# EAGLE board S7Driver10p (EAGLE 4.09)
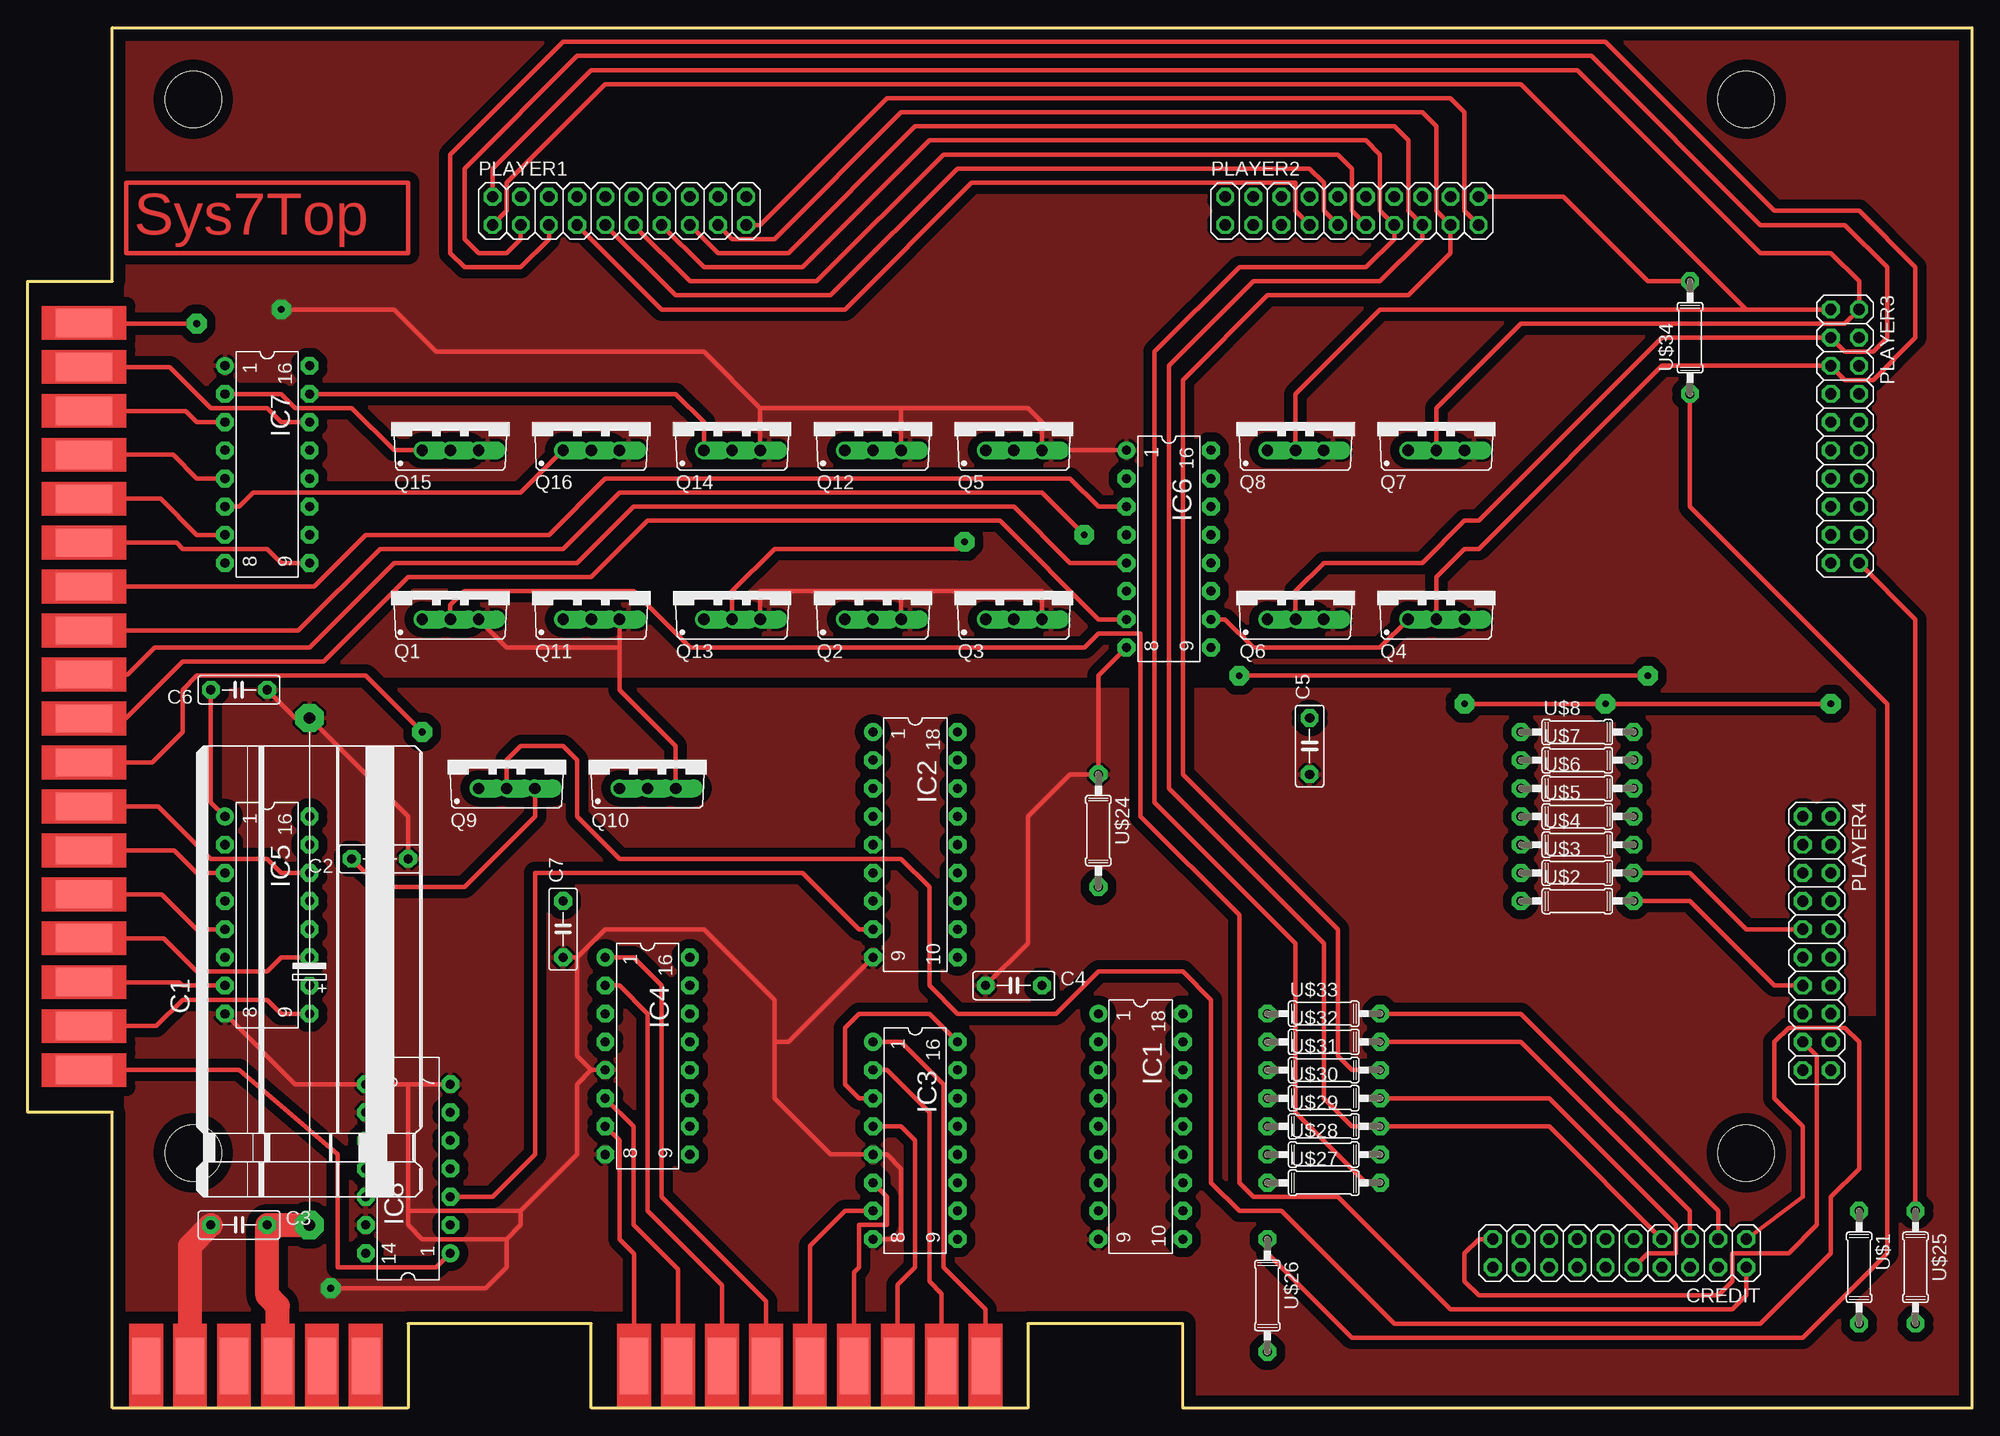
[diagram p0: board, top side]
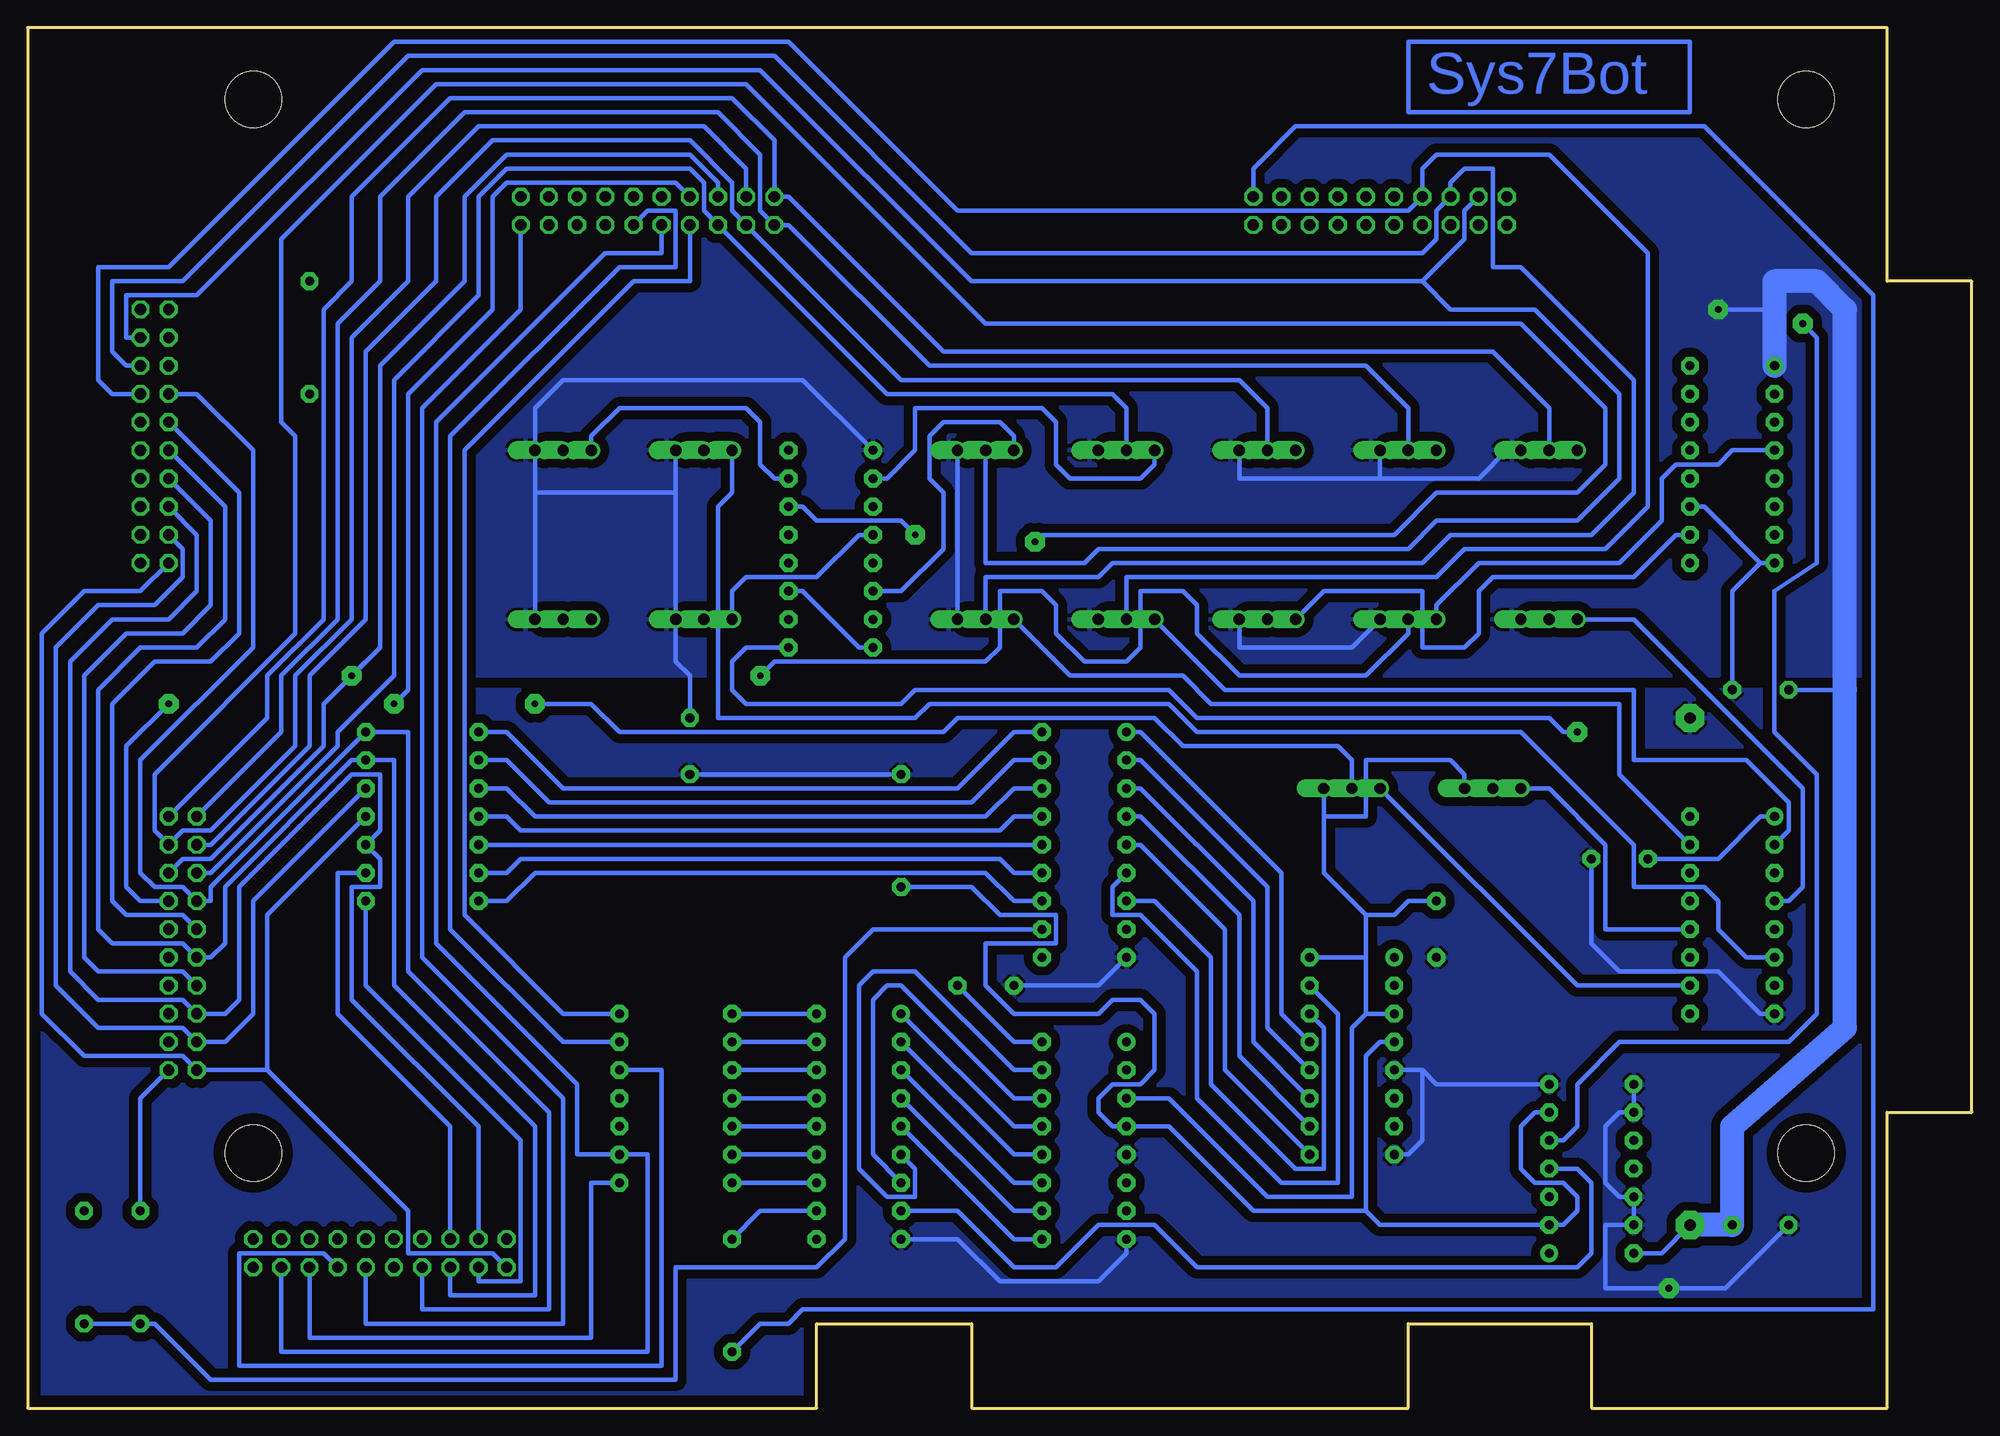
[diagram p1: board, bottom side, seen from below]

Size 175.26 x 124.46 mm. Coordinates in mm from the lower left corner, seen from the top.
Outline: 7.62,0 7.62,26.67 0,26.67 0,101.6 7.62,101.6 7.62,124.46 175.26,124.46 175.26,0 104.14,0 104.14,7.62 90.17,7.62 90.17,0 50.8,0 50.8,7.62 34.29,7.62 34.29,0 7.62,0
Copper layers used: Top, Bottom
Holes 5.08 mm at 14.92,23 154.92,23 154.92,118 14.92,118

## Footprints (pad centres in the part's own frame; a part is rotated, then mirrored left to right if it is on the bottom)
PLATINE9 = smd 2.54 x 5.08: 1 0,0; 2 3.962,0; 3 7.925,0; 4 11.887,0; 5 15.85,0; 6 19.812,0; 7 23.774,0; 8 27.737,0; 9 31.699,0
E-45 = drill 1.016 pad 2.54 octagon: 1 0,0; 2 45.72,0
C5B2,5 = drill 0.813 pad 1.6 octagon: 1 -2.54,0; 2 2.54,0
2X10 = drill 1.016 pad 1.6 octagon: 1 -11.43,-1.27; 2 -11.43,1.27; 3 -8.89,-1.27; 4 -8.89,1.27; 5 -6.35,-1.27; 6 -6.35,1.27; 7 -3.81,-1.27; 8 -3.81,1.27; 9 -1.27,-1.27; 10 -1.27,1.27; 11 1.27,-1.27; 12 1.27,1.27; 13 3.81,-1.27; 14 3.81,1.27; 15 6.35,-1.27; 16 6.35,1.27; 17 8.89,-1.27; 18 8.89,1.27; 19 11.43,-1.27; 20 11.43,1.27
DIL18 = drill 0.813 pad 1.6 round: 1 -10.16,-3.81 | drill 0.813 pad 1.6 octagon: 2 -7.62,-3.81; 3 -5.08,-3.81; 4 -2.54,-3.81; 5 0,-3.81; 6 2.54,-3.81; 7 5.08,-3.81; 8 7.62,-3.81; 9 10.16,-3.81; 10 10.16,3.81; 11 7.62,3.81; 12 5.08,3.81; 13 2.54,3.81; 14 0,3.81; 15 -2.54,3.81; 16 -5.08,3.81; 17 -7.62,3.81; 18 -10.16,3.81
DIL16 = drill 0.813 pad 1.6 round: 1 -8.89,-3.81 | drill 0.813 pad 1.6 octagon: 2 -6.35,-3.81; 3 -3.81,-3.81; 4 -1.27,-3.81; 5 1.27,-3.81; 6 3.81,-3.81; 7 6.35,-3.81; 8 8.89,-3.81; 9 8.89,3.81; 10 6.35,3.81; 11 3.81,3.81; 12 1.27,3.81; 13 -1.27,3.81; 14 -3.81,3.81; 15 -6.35,3.81; 16 -8.89,3.81
DIL14 = drill 0.813 pad 1.6 round: 1 -7.62,-3.81 | drill 0.813 pad 1.6 octagon: 2 -5.08,-3.81; 3 -2.54,-3.81; 4 0,-3.81; 5 2.54,-3.81; 6 5.08,-3.81; 7 7.62,-3.81; 8 7.62,3.81; 9 5.08,3.81; 10 2.54,3.81; 11 0,3.81; 12 -2.54,3.81; 13 -5.08,3.81; 14 -7.62,3.81
PLATINE6 = smd 2.54 x 5.08: 1 0,0; 2 3.962,0; 3 7.925,0; 4 11.887,0; 5 15.85,0; 6 19.812,0
TO220BS = drill 1.016 pad 1.626 offset: D 0,-2.54; G -2.54,-2.54; S 2.54,-2.54
PLTINE18 = smd 2.54 x 5.08: 1 0,0; 2 3.962,0; 3 7.925,0; 4 11.887,0; 5 15.85,0; 6 19.812,0; 7 23.774,0; 8 27.737,0; 9 31.699,0; 10 35.662,0; 11 39.624,0; 12 43.586,0; 13 47.549,0; 14 51.511,0; 15 55.474,0; 16 59.436,0; 17 63.398,0; 18 67.361,0
0207/10 = drill 0.813 pad 1.6 octagon: 1 -5.08,0; 2 5.08,0

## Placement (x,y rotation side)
BCD-IN  PADROW9  [PLATINE9]  86.36,3.81 180 top
C1  ELC-45  [E-45]  25.4,16.51 90 top
C2  C2,5  [C5B2,5]  31.75,49.53 180 top
C3  C2,5  [C5B2,5]  19.05,16.51 0 top
C4  C2,5  [C5B2,5]  88.9,38.1 0 top
C5  C2,5  [C5B2,5]  115.57,59.69 90 top
C6  C2,5  [C5B2,5]  19.05,64.77 180 top
C7  C2,5  [C5B2,5]  48.26,43.18 90 top
CREDIT  PINHD-2X10  [2X10]  143.51,13.97 180 top
IC1  ULN2803  [DIL18]  100.33,25.4 270 top
IC2  ULN2803  [DIL18]  80.01,50.8 270 top
IC3  4511  [DIL16]  80.01,24.13 270 top
IC4  4511  [DIL16]  55.88,31.75 270 top
IC5  4050  [DIL16]  21.59,44.45 270 top
IC6  4050  [DIL16]  102.87,77.47 270 top
IC7  4050  [DIL16]  21.59,85.09 270 top
IC8  4081  [DIL14]  34.29,21.59 90 top
PLAYER1  PINHD-2X10  [2X10]  53.34,107.95 0 top
PLAYER2  PINHD-2X10  [2X10]  119.38,107.95 0 top
PLAYER3  PINHD-2X10  [2X10]  163.83,87.63 270 top
PLAYER4  PINHD-2X10  [2X10]  161.29,41.91 270 top
POWER  PADROW6  [PLATINE6]  30.48,3.81 180 top
Q1  IRF????  [TO220BS]  38.1,73.66 0 top
Q2  IRF????  [TO220BS]  76.2,73.66 0 top
Q3  IRF????  [TO220BS]  88.9,73.66 0 top
Q4  IRF????  [TO220BS]  127,73.66 0 top
Q5  IRF????  [TO220BS]  88.9,88.9 0 top
Q6  IRF????  [TO220BS]  114.3,73.66 0 top
Q7  IRF????  [TO220BS]  127,88.9 0 top
Q8  IRF????  [TO220BS]  114.3,88.9 0 top
Q9  IRF????  [TO220BS]  43.18,58.42 0 top
Q10  IRF????  [TO220BS]  55.88,58.42 0 top
Q11  IRF????  [TO220BS]  50.8,73.66 0 top
Q12  IRF????  [TO220BS]  76.2,88.9 0 top
Q13  IRF????  [TO220BS]  63.5,73.66 0 top
Q14  IRF????  [TO220BS]  63.5,88.9 0 top
Q15  IRF????  [TO220BS]  38.1,88.9 0 top
Q16  IRF????  [TO220BS]  50.8,88.9 0 top
STROBE  PADROW18  [PLTINE18]  5.08,30.48 90 top
U$1  R1206  [0207/10]  165.1,12.7 270 top
U$2  R1206  [0207/10]  139.7,45.72 0 top
U$3  R1206  [0207/10]  139.7,48.26 0 top
U$4  R1206  [0207/10]  139.7,50.8 0 top
U$5  R1206  [0207/10]  139.7,53.34 0 top
U$6  R1206  [0207/10]  139.7,55.88 0 top
U$7  R1206  [0207/10]  139.7,58.42 0 top
U$8  R1206  [0207/10]  139.7,60.96 0 top
U$24  6.8K  [0207/10]  96.52,52.07 270 top
U$25  R1206  [0207/10]  170.18,12.7 270 top
U$26  R1206  [0207/10]  111.76,10.16 270 top
U$27  R1206  [0207/10]  116.84,20.32 0 top
U$28  R1206  [0207/10]  116.84,22.86 0 top
U$29  R1206  [0207/10]  116.84,25.4 0 top
U$30  R1206  [0207/10]  116.84,27.94 0 top
U$31  R1206  [0207/10]  116.84,30.48 0 top
U$32  R1206  [0207/10]  116.84,33.02 0 top
U$33  R1206  [0207/10]  116.84,35.56 0 top
U$34  R1206  [0207/10]  149.86,96.52 90 top

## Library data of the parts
BCD-IN POWER STROBE = SPECIAL
C1 = DISCRETE
C2-C7 = CAP
CREDIT PLAYER1-PLAYER4 = PINHEAD
IC1-IC4 = ULN
IC5-IC8 = 40XX
Q1-Q16 = TRANS-PW
U$1-U$8 U$24-U$34 = R

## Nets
BLANKING: BCD-IN.3 IC3.4 IC4.4 IC8.2 IC8.6 U$24.2
GND: C1.2 C2.1 C3.1 C4.1 C5.1 C6.1 C7.1 IC1.9 IC2.9 IC3.5 IC3.8 IC4.5 IC4.8 IC5.8 IC6.8 IC6.11 IC7.8 IC7.11 IC8.7 IC8.8 IC8.9 IC8.12 IC8.13 POWER.5 U$24.1
KOMMA1: PLAYER1.20 U$26.2
KOMMA2: PLAYER2.20 U$34.2
KOMMA3: PLAYER3.20 U$25.1
KOMMA4: PLAYER4.20 U$1.1
KOMMA12: IC8.5 STROBE.18
KOMMA34: IC8.1 STROBE.1
N$1: IC1.11 U$26.1 U$34.1
N$2: IC1.12 U$27.1
N$3: IC1.13 U$28.1
N$4: IC1.14 U$29.1
N$5: IC1.15 U$30.1
N$6: IC1.16 U$31.1
N$7: IC1.17 U$32.1
N$8: IC1.18 U$33.1
N$9: IC2.11 U$1.2 U$25.2
N$10: IC2.14 U$4.1
N$11: IC2.15 U$5.1
N$12: IC2.16 U$6.1
N$13: IC2.17 U$7.1
N$14: IC2.18 U$8.1
N$15: IC2.12 U$2.1
N$16: IC2.13 U$3.1
N$17: BCD-IN.2 IC3.2
N$18: BCD-IN.4 IC3.6
N$19: BCD-IN.5 IC3.7
N$20: BCD-IN.6 IC4.1
N$21: BCD-IN.7 IC4.2
N$22: BCD-IN.8 IC4.6
N$23: BCD-IN.9 IC4.7
N$24: IC1.8 IC8.4
N$25: BCD-IN.1 IC3.1
N$26: IC5.12 Q9.G
N$27: IC5.10 Q10.G
N$28: IC7.4 Q11.G
N$29: IC6.2 Q12.G
N$30: IC7.10 Q13.G
N$31: IC7.15 Q14.G
N$32: IC7.2 Q15.G
N$33: IC7.6 Q16.G
N$34: IC5.4 Q1.G
N$35: IC5.2 Q2.G
N$36: IC5.15 Q3.G
N$37: IC6.10 Q4.G
N$38: IC6.6 Q5.G
N$39: IC6.4 Q6.G
N$40: IC6.15 Q7.G
N$41: IC5.6 Q8.G
N$48: IC2.8 IC8.3
P1A: CREDIT.3 PLAYER1.7 PLAYER2.7 U$33.2
P1B: CREDIT.5 PLAYER1.11 PLAYER2.11 U$32.2
P1C: CREDIT.8 PLAYER1.17 PLAYER2.17 U$31.2
P1D: CREDIT.10 PLAYER1.19 PLAYER2.19 U$30.2
P1E: CREDIT.7 PLAYER1.15 PLAYER2.15 U$29.2
P1F: CREDIT.4 PLAYER1.9 PLAYER2.9 U$28.2
P1G: CREDIT.6 PLAYER1.13 PLAYER2.13 U$27.2
P2A: CREDIT.14 PLAYER3.7 PLAYER4.7 U$8.2
P2B: CREDIT.16 PLAYER3.11 PLAYER4.11 U$7.2
P2C: CREDIT.19 PLAYER3.17 PLAYER4.17 U$6.2
P2D: CREDIT.20 PLAYER3.19 PLAYER4.19 U$5.2
P2E: CREDIT.17 PLAYER3.15 PLAYER4.15 U$4.2
P2F: CREDIT.15 PLAYER3.9 PLAYER4.9 U$3.2
P2G: CREDIT.18 PLAYER3.13 PLAYER4.13 U$2.2
STR1: CREDIT.2 Q1.D
STR2: PLAYER1.8 PLAYER3.8 Q2.D
STR3: PLAYER1.6 PLAYER3.6 Q3.D
STR4: PLAYER1.5 PLAYER3.5 Q4.D
STR5: PLAYER1.4 PLAYER3.4 Q5.D
STR6: PLAYER1.3 PLAYER3.3 Q6.D
STR7: PLAYER1.2 PLAYER3.2 Q7.D
STR8: PLAYER1.1 PLAYER3.1 Q8.D
STR9: CREDIT.1 Q9.D
STR10: PLAYER2.8 PLAYER4.8 Q10.D
STR11: PLAYER2.6 PLAYER4.6 Q11.D
STR12: PLAYER2.5 PLAYER4.5 Q12.D
STR13: PLAYER2.4 PLAYER4.4 Q13.D
STR14: PLAYER2.3 PLAYER4.3 Q14.D
STR15: PLAYER2.2 PLAYER4.2 Q15.D
STR16: PLAYER2.1 PLAYER4.1 Q16.D
VCC: C1.1 C2.2 C3.2 C4.2 C5.2 C6.2 C7.2 IC3.3 IC3.16 IC4.3 IC4.16 IC5.1 IC6.1 IC7.1 IC8.14 POWER.3 Q1.S Q2.S Q3.S Q4.S Q5.S Q6.S Q7.S Q8.S Q9.S Q10.S Q11.S Q12.S Q13.S Q14.S Q15.S Q16.S
W1A: IC1.1 IC3.13
W1B: IC1.2 IC3.12
W1C: IC1.3 IC3.11
W1D: IC1.4 IC3.10
W1E: IC1.5 IC3.9
W1F: IC1.6 IC3.15
W1G: IC1.7 IC3.14
W2A: IC2.1 IC4.13
W2B: IC2.2 IC4.12
W2C: IC2.3 IC4.11
W2D: IC2.4 IC4.10
W2E: IC2.5 IC4.9
W2F: IC2.6 IC4.15
W2G: IC2.7 IC4.14
WSTR1: IC5.5 STROBE.5
WSTR2: IC5.3 STROBE.6
WSTR3: IC5.14 STROBE.7
WSTR4: IC6.9 STROBE.8
WSTR5: IC6.7 STROBE.9
WSTR6: IC6.5 STROBE.10
WSTR7: IC6.14 STROBE.11
WSTR8: IC5.7 STROBE.3
WSTR9: IC5.11 STROBE.4
WSTR10: IC5.9 STROBE.2
WSTR11: IC7.5 STROBE.15
WSTR12: IC6.3 STROBE.12
WSTR13: IC7.9 STROBE.13
WSTR14: IC7.14 STROBE.17
WSTR15: IC7.3 STROBE.16
WSTR16: IC7.7 STROBE.14

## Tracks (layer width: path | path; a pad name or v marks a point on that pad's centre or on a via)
BLANKING
  Top 0.406: IC3.4 78.74,25.4 80.01,24.13 80.01,12.7 78.44,11.12 BCD-IN.3
  Bottom 0.406: IC4.4 53.34,33.02 54.61,31.75 54.61,17.78 | 54.61,17.78 64.77,17.78 72.39,25.4 IC3.4 77.47,25.4 78.74,26.67 78.74,27.94 77.47,29.21 74.93,29.21 73.66,30.48 73.66,35.56 74.93,36.83 77.47,36.83 78.74,35.56 86.36,35.56 88.9,38.1 88.9,41.91 82.55,41.91 82.55,44.45 87.63,44.45 90.17,46.99 U$24.2 | 54.61,17.78 53.34,16.51 IC8.2 36.83,16.51 35.56,17.78 35.56,19.05 36.83,20.32 39.37,20.32 40.64,21.59 40.64,25.4 39.37,26.67 IC8.6
GND  (via drill 0.61 pad 1.78)
  Top 0.406: 67.31,33.02 67.31,27.94 72.39,22.86 IC3.5 77.47,22.86 78.74,21.59 78.74,15.24 IC3.8 | 67.31,33.02 67.31,36.83 60.96,43.18 52.07,43.18 49.53,40.64 | 49.53,40.64 49.53,31.75 50.8,30.48 | 50.8,30.48 IC4.5 | IC5.8 24.13,29.21 IC8.8 34.29,29.21 | 34.29,29.21 IC8.7 | 67.31,33.02 68.58,33.02 IC2.9 | IC6.8 96.52,66.04 U$24.1 93.98,57.15 90.17,53.34 90.17,41.91 C4.1 | 49.53,40.64 C7.1 | 50.8,30.48 49.53,29.21 49.53,22.86 44.45,17.78 | 44.45,17.78 44.45,16.51 43.18,15.24 | 43.18,15.24 35.56,15.24 34.29,16.51 34.29,17.78 | 34.29,17.78 34.29,29.21 | 44.45,17.78 34.29,17.78 | C6.1 24.13,62.23 C1.2 34.29,53.34 C2.1 | v27.3,10.79 41.27,10.79 43.18,12.7 43.18,15.24
  Top 2.184: POWER.5 14.63,14.63 C3.1
  Bottom 0.406: IC7.11 24.13,81.28 19.05,76.2 | 19.05,76.2 IC7.8 | IC8.8 IC8.9 31.75,26.67 33.02,25.4 33.02,20.32 31.75,19.05 IC8.12 IC8.13 33.02,16.51 33.02,10.79 v27.3,10.79 22.23,10.79 C3.1 | IC8.7 48.26,29.21 49.53,30.48 | IC4.5 49.53,30.48 | IC4.8 50.8,22.86 49.53,24.13 49.53,30.48 | IC6.11 105.41,73.66 100.33,68.58 IC6.8 | IC3.8 76.2,13.97 78.74,11.43 87.63,11.43 91.44,15.24 IC1.9 | 19.05,76.2 21.59,73.66 C6.1 | IC5.8 19.05,35.56 22.86,39.37 31.75,39.37 34.29,41.91 C2.1 | U$24.1 C5.1 | IC2.9 78.74,38.1 C4.1
  pour Bottom (isolate 0.8): 8.89,8.89 8.89,64.77 137.16,64.77 137.16,91.44 50.8,91.44 50.8,124.46 175.26,124.46 175.26,0 104.14,0 104.14,8.89
  pour Top (isolate 0.8): 8.89,8.89 8.89,64.77 140.97,64.77 140.97,124.46 175.26,124.46 175.26,0 104.14,0 104.14,8.89
KOMMA1
  Bottom 0.406: U$26.2 109.22,7.62 106.68,7.62 105.41,8.89 8.89,8.89 8.89,100.33 24.13,115.57 60.96,115.57 64.77,111.76 PLAYER1.20
KOMMA2
  Top 0.406: PLAYER2.20 138.43,109.22 146.05,101.6 U$34.2
KOMMA3
  Top 0.406: PLAYER3.20 170.18,71.12 U$25.1
KOMMA4
  Bottom 0.406: U$1.1 165.1,27.94 PLAYER4.20
KOMMA12  (via drill 0.61 pad 1.78)
  Top 0.406: STROBE.18 5.08,97.79 v15.24,97.79
  Bottom 0.406: IC8.5 36.83,24.13 35.56,25.4 35.56,29.21 31.75,33.02 16.51,33.02 13.97,35.56 13.97,57.15 17.78,60.96 17.78,73.66 13.97,76.2 13.97,96.52 v15.24,97.79
KOMMA34
  Top 0.406: STROBE.1 19.05,30.48 27.94,22.86 27.94,12.7 36.83,12.7 IC8.1
N$1
  Top 0.406: U$26.1 111.76,13.97 119.38,6.35 160.02,6.35 167.64,13.97 167.64,63.5 149.86,81.28 U$34.1
  Bottom 0.406: IC1.11 109.22,17.78 U$26.1
N$2
  Bottom 0.406: IC1.12 U$27.1
N$3
  Bottom 0.406: IC1.13 U$28.1
N$4
  Bottom 0.406: IC1.14 U$29.1
N$5
  Bottom 0.406: IC1.15 U$30.1
N$6
  Bottom 0.406: IC1.16 U$31.1
N$7
  Bottom 0.406: IC1.17 U$32.1
N$8
  Bottom 0.406: IC1.18 U$33.1
N$9
  Bottom 0.406: U$25.2 U$1.2 163.83,7.62 158.75,2.54 116.84,2.54 116.84,12.7 104.14,12.7 101.6,15.24 101.6,40.64 99.06,43.18 IC2.11
N$10
  Bottom 0.406: IC2.14 U$4.1
N$11
  Bottom 0.406: IC2.15 86.36,53.34 87.63,52.07 130.81,52.07 132.08,53.34 U$5.1
N$12
  Bottom 0.406: IC2.16 86.36,55.88 88.9,53.34 129.54,53.34 132.08,55.88 U$6.1
N$13
  Bottom 0.406: IC2.17 86.36,58.42 90.17,54.61 128.27,54.61 132.08,58.42 U$7.1
N$14
  Bottom 0.406: IC2.18 86.36,60.96 91.44,55.88 127,55.88 132.08,60.96 U$8.1
N$15
  Bottom 0.406: IC2.12 86.36,45.72 88.9,48.26 129.54,48.26 132.08,45.72 U$2.1
N$16
  Bottom 0.406: IC2.13 86.36,48.26 87.63,49.53 130.81,49.53 132.08,48.26 U$3.1
N$17
  Top 0.406: BCD-IN.2 82.4,10.31 81.28,11.43 81.28,26.67 77.47,30.48 IC3.2
N$18
  Top 0.406: IC3.6 77.47,19.05 77.47,16.51 74.93,16.51 74.93,12.7 74.47,12.24 BCD-IN.4
N$19
  Top 0.406: BCD-IN.5 70.51,14.63 73.66,17.78 IC3.7
N$20
  Top 0.406: BCD-IN.6 66.55,9.65 57.15,19.05 57.15,38.1 54.61,40.64 IC4.1
N$21
  Top 0.406: BCD-IN.7 62.59,11.07 55.88,17.78 55.88,35.56 53.34,38.1 IC4.2
N$22
  Top 0.406: BCD-IN.8 58.62,12.5 54.61,16.51 54.61,25.4 IC4.6
N$23
  Top 0.406: BCD-IN.9 54.66,13.92 53.34,15.24 53.34,24.13 IC4.7
N$24
  Bottom 0.406: IC8.4 35.56,21.59 34.29,20.32 34.29,13.97 35.56,12.7 69.85,12.7 73.66,16.51 78.74,16.51 82.55,12.7 86.36,12.7 91.44,17.78 IC1.8
N$25
  Top 0.406: BCD-IN.1 86.36,8.89 82.55,12.7 82.55,29.21 78.74,33.02 IC3.1
N$26
  Bottom 0.406: IC5.12 33.02,43.18 33.02,50.8 38.1,55.88 Q9.G
N$27
  Bottom 0.406: IC5.10 35.56,38.1 Q10.G
N$28
  Bottom 0.406: IC7.4 21.59,86.36 22.86,85.09 26.67,85.09 27.94,83.82 27.94,80.01 31.75,76.2 44.45,76.2 48.26,72.39 Q11.G
N$29
  Bottom 0.406: Q12.G 73.66,85.09 74.93,83.82 81.28,83.82 82.55,85.09 82.55,88.9 83.82,90.17 95.25,90.17 95.25,86.36 97.79,83.82 IC6.2
N$30
  Bottom 0.406: IC7.10 26.67,78.74 30.48,74.93 43.18,74.93 44.45,73.66 44.45,69.85 45.72,68.58 49.53,68.58 49.53,73.66 58.42,73.66 Q13.G
N$31
  Top 0.406: IC7.15 58.42,91.44 60.96,88.9 Q14.G
N$32
  Top 0.406: IC7.2 22.86,91.44 24.13,90.17 29.21,90.17 33.02,86.36 Q15.G
N$33
  Top 0.406: IC7.6 19.05,81.28 20.32,82.55 44.45,82.55 Q16.G
N$34
  Bottom 0.406: IC5.4 16.51,45.72 15.24,46.99 15.24,55.88 30.48,71.12 Q1.G
N$35
  Bottom 0.406: IC5.2 16.51,52.07 16.51,54.61 20.32,58.42 30.48,58.42 30.48,64.77 67.31,64.77 Q2.G
N$36
  Bottom 0.406: IC5.15 31.75,57.15 31.75,63.5 68.58,63.5 71.12,66.04 81.28,66.04 Q3.G
N$37
  Top 0.406: IC6.10 107.95,71.12 110.49,68.58 121.92,68.58 Q4.G
N$38
  Bottom 0.406: Q5.G 86.36,87.63 87.63,88.9 92.71,88.9 93.98,87.63 93.98,83.82 92.71,82.55 92.71,77.47 96.52,73.66 IC6.6
N$39
  Bottom 0.406: IC6.4 100.33,78.74 104.14,74.93 110.49,74.93 111.76,73.66 Q6.G
N$40
  Bottom 0.406: IC6.15 107.95,83.82 109.22,85.09 109.22,88.9 110.49,90.17 121.92,90.17 124.46,87.63 Q7.G
N$41
  Bottom 0.406: IC5.6 20.32,40.64 22.86,43.18 22.86,45.72 24.13,46.99 30.48,46.99 30.48,50.8 40.64,60.96 69.85,60.96 72.39,63.5 93.98,63.5 95.25,62.23 113.03,62.23 113.03,81.28 111.76,82.55 Q8.G
N$42
  Bottom 0.406: 25.4,116.84 25.4,123.19 50.8,123.19 50.8,116.84 25.4,116.84
N$43
  Top 0.406: 8.89,104.14 8.89,110.49 34.29,110.49 34.29,104.14 8.89,104.14
N$48
  Top 0.406: IC8.3 41.91,19.05 45.72,22.86 45.72,48.26 69.85,48.26 74.93,43.18 IC2.8
P1A
  Top 0.406: CREDIT.3 152.4,17.78 134.62,35.56 U$33.2 | PLAYER2.7 114.3,107.95 114.3,110.49 85.09,110.49 73.66,99.06 57.15,99.06 PLAYER1.7
  Bottom 0.406: PLAYER2.7 115.57,101.6 120.65,101.6 135.89,86.36 135.89,44.45 127,35.56 U$33.2
P1B
  Top 0.406: CREDIT.5 149.86,17.78 134.62,33.02 U$32.2 | PLAYER1.11 59.69,101.6 71.12,101.6 82.55,113.03 118.11,113.03 119.38,111.76 119.38,107.95 PLAYER2.11
  Bottom 0.406: PLAYER2.11 119.38,107.95 116.84,107.95 116.84,102.87 121.92,102.87 137.16,87.63 137.16,43.18 127,33.02 U$32.2
P1C
  Top 0.406: PLAYER1.17 63.5,105.41 67.31,105.41 78.74,116.84 125.73,116.84 127,115.57 127,107.95 PLAYER2.17 128.27,104.14 124.46,100.33 111.76,100.33 104.14,92.71 104.14,57.15 118.11,43.18 118.11,31.75 119.38,30.48 U$31.2
  Bottom 0.406: CREDIT.8 148.59,13.97 156.21,13.97 156.21,3.81 118.11,3.81 118.11,30.48 U$31.2
P1D
  Top 0.406: PLAYER2.19 129.54,107.95 129.54,116.84 128.27,118.11 77.47,118.11 66.04,106.68 PLAYER1.19 | U$30.2 137.16,27.94 148.59,16.51 148.59,13.97 146.05,13.97 CREDIT.10
  Bottom 0.406: CREDIT.10 144.78,7.62 127,7.62 127,27.94 139.7,40.64 139.7,90.17 130.81,99.06 PLAYER2.19
P1E
  Top 0.406: CREDIT.7 137.16,25.4 U$29.2 119.38,25.4 116.84,27.94 116.84,41.91 102.87,55.88 102.87,93.98 110.49,101.6 121.92,101.6 125.73,105.41 PLAYER2.15 124.46,107.95 124.46,114.3 123.19,115.57 80.01,115.57 68.58,104.14 62.23,104.14 PLAYER1.15
P1F
  Top 0.406: PLAYER2.9 116.84,107.95 116.84,110.49 115.57,111.76 83.82,111.76 72.39,100.33 58.42,100.33 PLAYER1.9
  Bottom 0.406: CREDIT.4 152.4,5.08 119.38,5.08 119.38,22.86 U$28.2 125.73,22.86 125.73,29.21 138.43,41.91 138.43,88.9 123.19,104.14 118.11,104.14 PLAYER2.9
P1G
  Top 0.406: PLAYER1.13 60.96,102.87 69.85,102.87 81.28,114.3 120.65,114.3 121.92,113.03 121.92,107.95 PLAYER2.13 123.19,105.41 120.65,102.87 109.22,102.87 101.6,95.25 101.6,54.61 114.3,41.91 114.3,26.67 120.65,20.32 U$27.2
  Bottom 0.406: U$27.2 124.46,20.32 124.46,6.35 149.86,6.35 CREDIT.6
P2A
  Bottom 0.406: CREDIT.14 139.7,8.89 128.27,8.89 128.27,26.67 140.97,39.37 140.97,60.96 U$8.2 158.75,46.99 158.75,45.72 PLAYER4.7 161.29,46.99 163.83,46.99 165.1,48.26 165.1,58.42 154.94,68.58 154.94,86.36 160.02,91.44 PLAYER3.7
P2B
  Bottom 0.406: CREDIT.16 137.16,10.16 129.54,10.16 129.54,25.4 142.24,38.1 142.24,58.42 U$7.2 146.05,58.42 157.48,46.99 157.48,41.91 158.75,40.64 PLAYER4.11 161.29,41.91 167.64,41.91 168.91,43.18 168.91,64.77 165.1,68.58 160.02,68.58 157.48,71.12 157.48,81.28 PLAYER3.11
P2C
  Top 0.406: PLAYER4.17 161.29,31.75 161.29,16.51 158.75,13.97 153.67,13.97 153.67,11.43 152.4,10.16 130.81,10.16 129.54,11.43 129.54,13.97 130.81,15.24 CREDIT.19
  Bottom 0.406: U$6.2 154.94,45.72 154.94,35.56 157.48,33.02 PLAYER4.17 161.29,34.29 168.91,34.29 172.72,38.1 172.72,68.58 168.91,72.39 163.83,72.39 161.29,74.93 161.29,77.47 PLAYER3.17
P2D
  Bottom 0.406: CREDIT.20 133.35,13.97 140.97,13.97 140.97,17.78 153.67,30.48 | 153.67,30.48 PLAYER4.19 161.29,31.75 170.18,31.75 173.99,35.56 173.99,69.85 170.18,73.66 165.1,73.66 PLAYER3.19 | U$5.2 153.67,44.45 153.67,30.48
P2E
  Bottom 0.406: CREDIT.17 134.62,25.4 146.05,36.83 146.05,46.99 143.51,46.99 143.51,49.53 U$4.2 143.51,52.07 143.51,57.15 146.05,57.15 156.21,46.99 156.21,36.83 157.48,35.56 PLAYER4.15 161.29,36.83 168.91,36.83 171.45,39.37 171.45,67.31 167.64,71.12 162.56,71.12 160.02,73.66 160.02,78.74 PLAYER3.15
P2F
  Top 0.406: PLAYER4.9 154.94,43.18 149.86,48.26 U$3.2
  Bottom 0.406: CREDIT.15 137.16,25.4 147.32,35.56 147.32,48.26 U$3.2 | PLAYER3.9 156.21,82.55 156.21,69.85 158.75,67.31 163.83,67.31 167.64,63.5 167.64,45.72 166.37,44.45 161.29,44.45 PLAYER4.9
P2G
  Top 0.406: U$2.2 149.86,45.72 157.48,38.1 PLAYER4.13
  Bottom 0.406: CREDIT.18 134.62,11.43 130.81,11.43 130.81,24.13 144.78,38.1 U$2.2 | PLAYER3.13 158.75,80.01 158.75,72.39 161.29,69.85 166.37,69.85 170.18,66.04 170.18,40.64 168.91,39.37 161.29,39.37 PLAYER4.13
STR1
  Top 0.406: CREDIT.2 154.94,10.16 153.67,8.89 128.27,8.89 118.11,19.05 110.49,19.05 109.22,20.32 109.22,44.45 100.33,53.34 100.33,69.85 96.52,69.85 95.25,68.58 59.69,68.58 54.61,73.66 39.37,73.66 38.1,72.39 Q1.D
STR2
  Bottom 0.406: PLAYER3.8 167.64,91.44 168.91,92.71 168.91,102.87 162.56,102.87 142.24,123.19 106.68,123.19 91.44,107.95 50.8,107.95 PLAYER1.8 49.53,111.76 48.26,113.03 38.1,113.03 29.21,104.14 29.21,81.28 33.02,77.47 45.72,77.47 48.26,74.93 76.2,74.93 Q2.D
STR3
  Bottom 0.406: PLAYER3.6 166.37,93.98 167.64,95.25 167.64,101.6 161.29,101.6 140.97,121.92 107.95,121.92 90.17,104.14 49.53,104.14 48.26,105.41 48.26,107.95 PLAYER1.6 46.99,110.49 45.72,111.76 43.18,111.76 43.18,102.87 40.64,102.87 30.48,92.71 30.48,82.55 34.29,78.74 46.99,78.74 49.53,76.2 77.47,76.2 78.74,74.93 88.9,74.93 Q3.D
STR4
  Top 0.406: Q4.D 127,74.93 129.54,77.47 130.81,77.47 147.32,93.98 PLAYER3.5 163.83,92.71 166.37,92.71 170.18,96.52 170.18,102.87 165.1,107.95 157.48,107.95 142.24,123.19 48.26,123.19 38.1,113.03 38.1,104.14 39.37,102.87 44.45,102.87 46.99,105.41 PLAYER1.5
STR5
  Bottom 0.406: PLAYER3.4 166.37,96.52 166.37,100.33 160.02,100.33 139.7,120.65 109.22,120.65 90.17,101.6 49.53,101.6 | 49.53,101.6 45.72,105.41 45.72,107.95 PLAYER1.4 | Q5.D 88.9,76.2 80.01,76.2 78.74,77.47 50.8,77.47 48.26,80.01 35.56,80.01 31.75,83.82 31.75,91.44 39.37,99.06 46.99,99.06 49.53,101.6
STR6
  Top 0.406: Q6.D 114.3,73.66 116.84,76.2 125.73,76.2 129.54,80.01 130.81,80.01 147.32,96.52 PLAYER3.3 163.83,95.25 166.37,95.25 167.64,96.52 167.64,102.87 163.83,106.68 156.21,106.68 140.97,121.92 49.53,121.92 39.37,111.76 39.37,105.41 40.64,104.14 43.18,104.14 44.45,105.41 PLAYER1.3
STR7
  Top 0.406: Q7.D 127,90.17 134.62,97.79 163.83,97.79 PLAYER3.2 165.1,101.6 162.56,104.14 156.21,104.14 139.7,120.65 50.8,120.65 41.91,111.76 PLAYER1.2
STR8
  Top 0.406: 154.94,99.06 PLAYER3.1 | 154.94,99.06 121.92,99.06 114.3,91.44 Q8.D | PLAYER1.1 43.18,107.95 43.18,110.49 52.07,119.38 134.62,119.38 154.94,99.06
STR9
  Top 0.406: CREDIT.1 160.02,19.05 160.02,25.4 157.48,27.94 157.48,33.02 158.75,34.29 163.83,34.29 165.1,33.02 165.1,21.59 162.56,19.05 162.56,13.97 156.21,7.62 123.19,7.62 113.03,17.78 109.22,17.78 106.68,20.32 106.68,36.83 104.14,39.37 96.52,39.37 92.71,35.56 83.82,35.56 81.28,38.1 81.28,46.99 78.74,49.53 53.34,49.53 49.53,53.34 49.53,58.42 48.26,59.69 44.45,59.69 43.18,58.42 Q9.D
STR10  (via drill 0.61 pad 1.78)
  Top 0.406: v162.56,63.5 v142.24,63.5 v129.54,63.5
  Bottom 0.406: PLAYER2.8 116.84,110.49 132.08,110.49 133.35,109.22 133.35,99.06 140.97,91.44 140.97,64.77 v142.24,63.5 | PLAYER4.8 165.1,45.72 166.37,46.99 166.37,59.69 v162.56,63.5 | v129.54,63.5 124.46,63.5 121.92,60.96 92.71,60.96 91.44,62.23 73.66,62.23 71.12,59.69 57.15,59.69 55.88,58.42 Q10.D
STR11  (via drill 0.61 pad 1.78)
  Top 0.406: v109.22,66.04 v146.05,66.04
  Bottom 0.406: PLAYER4.6 161.29,49.53 158.75,49.53 148.59,59.69 148.59,63.5 143.51,68.58 | 143.51,68.58 143.51,93.98 135.89,101.6 135.89,109.22 132.08,113.03 115.57,113.03 113.03,110.49 PLAYER2.6 | Q11.D 50.8,69.85 54.61,66.04 66.04,66.04 69.85,69.85 69.85,72.39 71.12,73.66 74.93,73.66 74.93,68.58 76.2,67.31 80.01,67.31 82.55,69.85 82.55,72.39 83.82,73.66 87.63,73.66 87.63,68.58 88.9,67.31 107.95,67.31 v109.22,66.04 | v146.05,66.04 143.51,68.58
STR12
  Bottom 0.406: PLAYER4.5 158.75,48.26 147.32,59.69 147.32,60.96 142.24,66.04 142.24,92.71 134.62,100.33 134.62,109.22 132.08,111.76 115.57,111.76 114.3,110.49 114.3,107.95 PLAYER2.5 97.79,91.44 77.47,91.44 76.2,90.17 Q12.D
STR13  (via drill 0.61 pad 1.78)
  Top 0.406: v84.45,78.11 83.82,77.47 67.31,77.47 63.5,73.66 Q13.D
  Bottom 0.406: PLAYER2.4 110.49,111.76 114.3,115.57 134.62,115.57 140.97,109.22 140.97,101.6 146.05,96.52 146.05,71.12 151.13,66.04 151.13,59.69 158.75,52.07 161.29,52.07 PLAYER4.4 163.83,52.07 163.83,57.15 151.13,69.85 151.13,87.63 152.4,88.9 152.4,105.41 138.43,119.38 110.49,119.38 88.9,97.79 40.64,97.79 33.02,90.17 33.02,85.09 35.56,82.55 48.26,82.55 52.07,78.74 83.82,78.74 v84.45,78.11
STR14
  Bottom 0.406: PLAYER4.3 158.75,50.8 149.86,59.69 149.86,66.04 144.78,71.12 144.78,95.25 138.43,101.6 138.43,109.22 133.35,114.3 115.57,114.3 111.76,110.49 111.76,107.95 PLAYER2.3 96.52,92.71 66.04,92.71 63.5,90.17 Q14.D
STR15
  Bottom 0.406: PLAYER4.2 153.67,62.23 153.67,66.04 148.59,71.12 148.59,99.06 146.05,101.6 146.05,109.22 137.16,118.11 111.76,118.11 107.95,114.3 PLAYER2.2 106.68,109.22 92.71,95.25 43.18,95.25 38.1,90.17 Q15.D
STR16
  Bottom 0.406: PLAYER4.1 152.4,60.96 152.4,66.04 147.32,71.12 147.32,97.79 143.51,101.6 143.51,109.22 135.89,116.84 113.03,116.84 109.22,113.03 109.22,107.95 PLAYER2.1 106.68,106.68 93.98,93.98 54.61,93.98 50.8,90.17 Q16.D
VCC  (via drill 0.61 pad 1.78)
  Top 0.406: 66.04,90.17 Q14.S | 66.04,90.17 78.74,90.17 | 78.74,90.17 Q12.S | 78.74,90.17 90.17,90.17 91.44,88.9 Q5.S IC6.1 | Q3.S 91.44,73.66 78.74,73.66 | 78.74,73.66 Q2.S | Q13.S 66.04,73.66 78.74,73.66 | 53.34,68.58 Q11.S | 53.34,68.58 43.18,68.58 Q1.S | Q10.S 58.42,59.69 53.34,64.77 53.34,68.58 | C2.2 31.75,46.99 39.37,46.99 45.72,53.34 Q9.S | C6.2 16.51,54.61 IC5.1 | IC3.3 74.93,27.94 73.66,29.21 73.66,34.29 74.93,35.56 81.28,35.56 IC3.16 | 66.04,90.17 60.96,95.25 36.83,95.25 33.02,99.06 v22.86,99.06
  Top 2.184: POWER.3 22.55,9.2 21.59,10.16 C3.2 C1.1
  Bottom 0.406: 54.61,35.56 IC4.3 | 54.61,35.56 55.88,34.29 55.88,19.05 63.5,19.05 72.39,27.94 IC3.3 | 58.42,53.34 58.42,48.26 54.61,44.45 | 58.42,53.34 Q10.S | 54.61,44.45 54.61,40.64 | 54.61,40.64 54.61,35.56 | Q15.S 41.91,86.36 44.45,83.82 53.34,83.82 | 53.34,83.82 Q16.S | Q14.S 66.04,83.82 53.34,83.82 | Q5.S Q3.S | Q13.S 66.04,68.58 55.88,68.58 Q11.S | IC6.1 105.41,92.71 127,92.71 129.54,90.17 Q7.S 129.54,82.55 | 129.54,82.55 116.84,82.55 | 116.84,82.55 Q8.S | 116.84,82.55 Q6.S 116.84,67.31 115.57,66.04 C5.2 | 129.54,82.55 Q4.S | 11.43,64.77 C6.2 | C2.2 22.86,49.53 19.05,53.34 IC5.1 | Q9.S 45.72,57.15 46.99,58.42 54.61,58.42 54.61,53.34 58.42,53.34 | 54.61,40.64 IC4.16 | IC3.16 86.36,33.02 C4.2 | 54.61,44.45 52.07,44.45 50.8,45.72 C7.2 | C1.1 27.94,13.97 IC8.14 | 17.78,99.06 v22.86,99.06
  Bottom 2.184: IC7.1 17.78,99.06 17.78,101.6 13.97,101.6 11.43,99.06 11.43,64.77 11.43,34.29 21.59,25.4 C3.2 C1.1
  pour Top (isolate 0.8): 8.89,123.19 8.89,66.04 144.78,66.04 144.78,35.56 171.45,35.56 171.45,106.68 138.43,106.68 138.43,123.19
  pour Bottom (isolate 0.8): 8.89,124.46 8.89,66.04 143.51,66.04 143.51,124.46
W1A
  Bottom 0.406: IC3.13 86.36,25.4 IC1.1
W1B
  Bottom 0.406: IC3.12 86.36,22.86 IC1.2
W1C
  Bottom 0.406: IC3.11 86.36,20.32 IC1.3
W1D
  Bottom 0.406: IC3.10 86.36,17.78 IC1.4
W1E
  Bottom 0.406: IC3.9 86.36,15.24 IC1.5
W1F
  Bottom 0.406: IC3.15 86.36,30.48 95.25,39.37 99.06,39.37 100.33,38.1 100.33,21.59 97.79,19.05 95.25,19.05 95.25,21.59 IC1.6
W1G
  Bottom 0.406: IC3.14 86.36,27.94 96.52,38.1 97.79,38.1 99.06,36.83 99.06,22.86 IC1.7
W2A
  Bottom 0.406: IC4.13 62.23,35.56 62.23,48.26 74.93,60.96 IC2.1
W2B
  Bottom 0.406: IC4.12 63.5,34.29 63.5,46.99 74.93,58.42 IC2.2
W2C
  Bottom 0.406: IC4.11 64.77,33.02 64.77,45.72 74.93,55.88 IC2.3
W2D
  Bottom 0.406: IC4.10 66.04,31.75 66.04,44.45 74.93,53.34 IC2.4
W2E
  Bottom 0.406: IC4.9 67.31,30.48 67.31,43.18 74.93,50.8 IC2.5
W2F
  Bottom 0.406: IC4.15 57.15,35.56 57.15,20.32 62.23,20.32 69.85,27.94 69.85,39.37 74.93,44.45 77.47,44.45 77.47,46.99 IC2.6
W2G
  Bottom 0.406: IC4.14 58.42,34.29 58.42,21.59 60.96,21.59 68.58,29.21 68.58,40.64 73.66,45.72 IC2.7
WSTR1
  Top 0.406: STROBE.5 12.09,46.33 15.24,43.18 IC5.5
WSTR2
  Top 0.406: STROBE.6 13.21,50.29 15.24,48.26 IC5.3
WSTR3
  Top 0.406: STROBE.7 11.79,54.25 16.51,49.53 21.59,49.53 22.86,48.26 IC5.14
WSTR4  (via drill 0.61 pad 1.78)
  Top 0.406: STROBE.8 11.23,58.22 13.97,60.96 13.97,64.77 15.24,66.04 30.48,66.04 v35.56,60.96
  Bottom 0.406: IC6.9 110.49,68.58 111.76,67.31 111.76,64.77 110.49,63.5 96.52,63.5 95.25,64.77 72.39,64.77 69.85,62.23 38.1,62.23 36.83,60.96 v35.56,60.96
WSTR5
  Top 0.406: IC6.7 96.52,71.12 87.63,80.01 55.88,80.01 50.8,74.93 34.29,74.93 26.67,67.31 13.97,67.31 8.84,62.18 STROBE.9
WSTR6
  Top 0.406: IC6.5 93.98,76.2 88.9,81.28 54.61,81.28 49.53,76.2 33.02,76.2 25.4,68.58 11.43,68.58 8.99,66.14 STROBE.10
WSTR7  (via drill 0.61 pad 1.78)
  Top 0.406: STROBE.11 24.38,70.1 31.75,77.47 48.26,77.47 53.34,82.55 91.44,82.55 v95.25,78.74
  Bottom 0.406: v95.25,78.74 96.52,80.01 104.14,80.01 105.41,81.28 IC6.14
WSTR8
  Top 0.406: STROBE.3 13.66,38.41 13.97,38.1 IC5.7
WSTR9
  Top 0.406: STROBE.4 12.24,42.37 15.24,39.37 21.59,39.37 22.86,40.64 IC5.11
WSTR10
  Top 0.406: STROBE.2 11.58,34.44 13.97,36.83 21.59,36.83 22.86,35.56 IC5.9
WSTR11
  Top 0.406: STROBE.15 13.11,85.95 15.24,83.82 IC7.5
WSTR12
  Top 0.406: STROBE.12 25.81,74.07 30.48,78.74 46.99,78.74 52.07,83.82 93.98,83.82 96.52,81.28 IC6.3
WSTR13
  Top 0.406: STROBE.13 13.41,78.03 13.97,77.47 21.59,77.47 22.86,76.2 IC7.9
WSTR14
  Top 0.406: STROBE.17 12.8,93.88 16.51,90.17 21.59,90.17 22.86,88.9 IC7.14
WSTR15
  Top 0.406: STROBE.16 14.22,89.92 15.24,88.9 IC7.3
WSTR16
  Top 0.406: STROBE.14 11.99,81.99 15.24,78.74 IC7.7

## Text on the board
Top: Sys7Top
Bottom: Sys7Bot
